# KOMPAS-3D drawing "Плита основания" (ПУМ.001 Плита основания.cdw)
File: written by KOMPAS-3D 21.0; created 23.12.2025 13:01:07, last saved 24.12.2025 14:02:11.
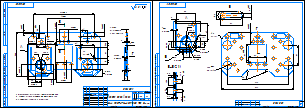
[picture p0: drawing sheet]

Sheets 1-2: A4x2, landscape

Document properties: Автор: User; Знак неуказанной шероховатости: 4; Параметр неуказанной шероховатости: 2,5; Масса: 0.21633; Форматы листов документа: 2xA4@4~2

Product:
- Part/product: Плита основания
    Материал: АМг6  ГОСТ 4784-2019 (density 2650 kg/m3)
    Масса: 0.21633
    Форматы листов документа: 2xA4@4~2

Title block, sheet 1: Наименование: Плита основания; designation: ПУМ.001; Материал: АМг6  ГОСТ 4784-2019; Масса: 0,22; sheet number: 1; Количество листов документа: 2; organisation: ООО ТПК Пегас; Форматы листов документа: A4 2; stored path: C:\Users\User\Desktop\ПУ\ПУМ\Чертежи\ПУМ.001 Плита основания.cdw; Разработал: Гайсин
Title block, sheet 2: sheet number: 2

Views: Вид 1, Сверху, Выносной элемент 4, Выносной элемент 5, Разрез В-В, Проекционный вид 7, Местный разрез 1, Местный разрез 2, Вид по стрелке 8, Выносной элемент А, Выносной элемент, Выносной элемент Б, Вид по стрелке Г
Referenced files in C:\Users\User\Desktop\ПУ\ПУМ\: ПУМ.001 Плита основания.m3d
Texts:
  по контуру
  с 2-х сторон
Dimensions and other numbers on the sheet: 122; 13±0,1; 5±0,1; 24±0,1; 12; 32±0,1; 168±0,1; 90±0,1; 30; 22,5; 18; 6 мест; 7,5±0,1; 36±0,1; 40±0,1; 5,5±0,1; 17; 39; 8; 10 отв; 23,55; 15; 19; 17,5; 3; 4 рад; 1; 2,5; 4 места; 6; 2 места; 54; 1,5; 16 рад; 9; 16; 49; 6-7Н; 2 отв; 10,4; 5,2; 10; 2,8; 6 отв; 3,3; 6,2; 5 отв; 2; 4; 0,5; 2 фаски; 56; 25; 4 цековки; 200; 48; 50; 33±0,1; 10 рад; 1:1; 0,22

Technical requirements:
  Неуказанные предельные отклонения  0,2мм
  Острые кромки притупить фаской 0,2х45
  Остальные размеры с 3д-модели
